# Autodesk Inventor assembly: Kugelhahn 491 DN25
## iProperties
Company: CAD & Internet
Shininess: 64.0
Length Units: 11269
Angle Units: 11279
Time Units: 11290
Mass Units: 11283
Length Display Precision: 3
Angle Display Precision: 2
Compacted: True
Created: 2004-08
Part Number: Kugelhahn 491 DN25
Document SubType Name: Assembly
Designer: AG
Manufacturer: Standard
Standards Organization: Custom
Density: 0.0
Volumn: 0.0
Area: 0.0
PropertySet Name: Model Information
Control State: 0
Master: False
Checked Out: False
Author: Achorner Georg
